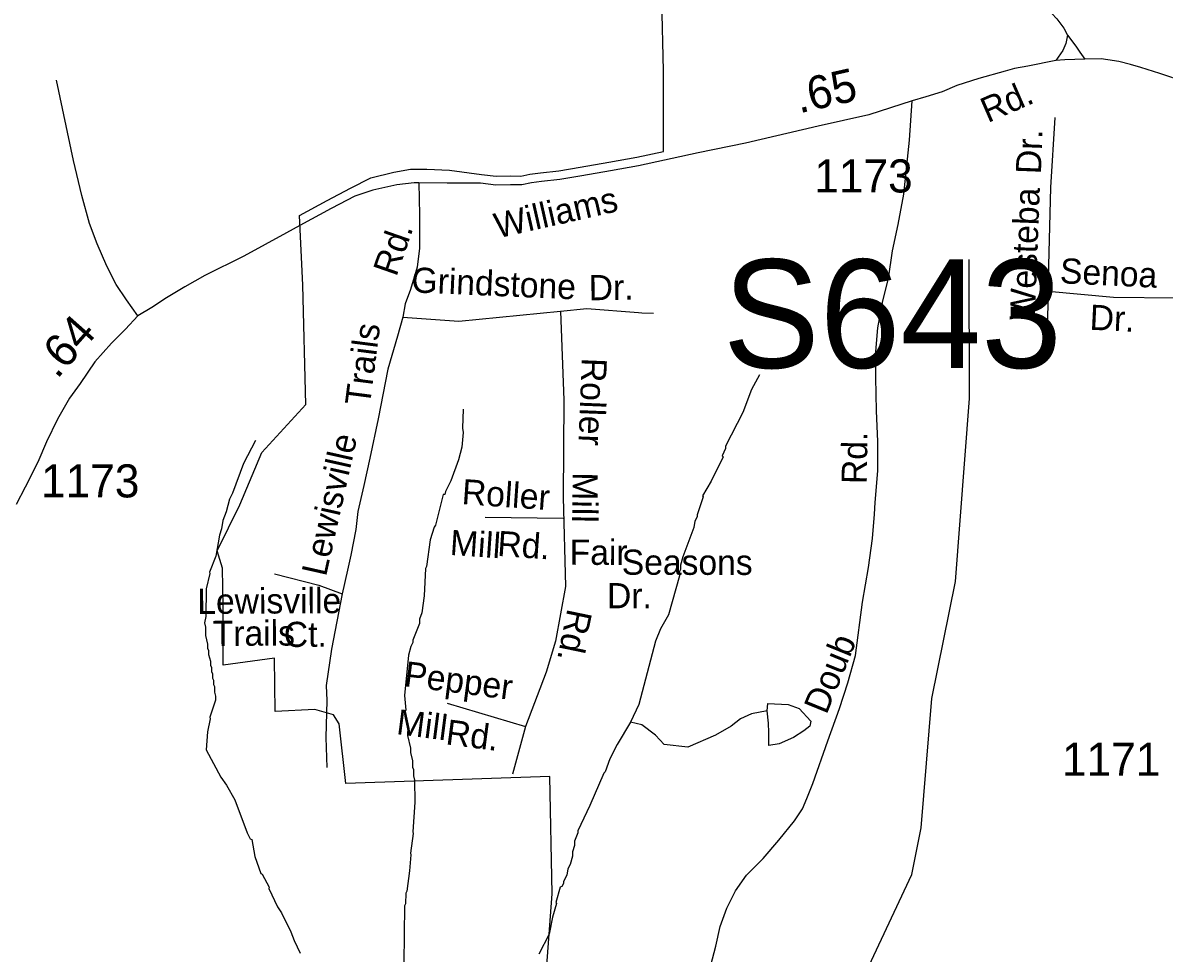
# Model space of a CAD drawing. Extents: x 1547597 to 1699558, y 810033 to 920809.
# Drawn here: x 1572833 to 1577144, y 851331 to 854845 of the extents above; entities that cross this region are included whole.
import ezdxf

# ---------------------------------------------------------------- set-up
doc = ezdxf.new("R2010")
doc.units = 0
for name, color, linetype in [('Exist Boundary Political City Limit New', 7, 'Continuous'), ('Exist Hydrographic Creek Single Shore', 7, 'Continuous'), ('Exist Hydrographic Misc Water Feature', 7, 'Continuous'), ('Exist Road Non-System Type 51', 7, 'Continuous'), ('Exist Road Non-System Type 51 Label', 7, 'Continuous'), ('Exist Road Primary Interstate Structure Ovrhead Sign Number Label', 7, 'Continuous'), ('Exist Road Primary US Ramp 1 Lane  Attributed', 7, 'Continuous'), ('Exist Road Secondary Mileage Hundredths English Label', 7, 'Continuous'), ('Exist Road Secondary Type 51 Attributed', 7, 'Continuous'), ('Exist Road Secondary Type 51 Label', 7, 'Continuous'), ('Exist Road Secondary Type 51 Number Label', 7, 'Continuous'), ('Map Preparation Boundary City Limit Buffer Line', 7, 'Continuous')]:
    doc.layers.add(name, color=color, linetype=linetype)

msp = doc.modelspace()

# ---------------------------------------------------------------- linework, layer by layer
at = {"layer": 'Exist Boundary Political City Limit New'}
msp.add_line((1574805.4, 851192.3), (1574832.2, 851554.6), dxfattribs=at)
msp.add_lwpolyline([(1574832.2, 851554.6), (1574824.2, 851997.9), (1574053, 851971), (1574027.8, 852197.3), (1574006.6, 852230.7), (1573936.2, 852251.3), (1573785.5, 852243.2), (1573783.2, 852444.9), (1573589.4, 852417.9), (1573590.2, 852639), (1573587, 852784.3), (1573566.9, 852850), (1573653.1, 853024.1), (1573735.3, 853221.6), (1573901.9, 853403.3), (1573890.4, 853853.6), (1573877.7, 854116.6), (1573982.1, 854173.1), (1574071.1, 854219.9), (1574147, 854258.7), (1574234.2, 854280.8), (1574296.8, 854292.6), (1574358.4, 854291.8), (1574445.1, 854288.6), (1574565.7, 854271.9), (1574621, 854265.3), (1574675.4, 854266.4), (1574714.3, 854265.9), (1574747.9, 854272.9), (1574787.9, 854278.7), (1574857.3, 854285.4), (1574938.4, 854300), (1575046.9, 854318.5), (1575152.4, 854336.8), (1575252.9, 854358.6), (1575252.4, 854662.9), (1575247, 854934.5)], dxfattribs=at)
at = {"layer": 'Exist Hydrographic Creek Single Shore'}
msp.add_lwpolyline([(1572780, 849528.5), (1573518.6, 849772.1), (1573732.5, 850003.6), (1573884.4, 850151.5), (1574087.9, 850283.4), (1574357.2, 850346.4), (1574788.5, 850389.2), (1575358.5, 850591.1), (1575509.5, 850679.9), (1575750.8, 850960.4), (1575874.1, 851087.1), (1575927.5, 851209.3), (1576009.4, 851241), (1576190.5, 851628), (1576226.4, 851804.6), (1576266.5, 852292.9), (1576356.4, 852734.2), (1576408.5, 853425.8), (1576407.5, 853951)], dxfattribs=at)
at = {"layer": 'Exist Hydrographic Misc Water Feature'}
for points in [[(1575616.2, 853515.6), (1575585.6, 853460), (1575552.5, 853372.4), (1575487, 853245.3), (1575486.9, 853237.3), (1575474.6, 853209.5), (1575478.5, 853205.4), (1575433.4, 853114), (1575400.8, 853058.4), (1575402.3, 853054), (1575380, 852986.8), (1575379.9, 852978.8), (1575371.7, 852962.9), (1575367.4, 852939), (1575326.1, 852827.5), (1575317.7, 852795.6), (1575317.6, 852779.6), (1575313.5, 852771.7), (1575313.2, 852755.7), (1575271.5, 852608.3), (1575241.8, 852555.2), (1575222.3, 852509), (1575159.5, 852269.8), (1575128.4, 852202.8)], [(1574496.8, 853385.7), (1574494, 853313.7), (1574495.8, 853297.7), (1574491.2, 853241.8), (1574478.6, 853194), (1574449.7, 853114.4), (1574429.2, 853074.7), (1574427, 853062.7), (1574421.1, 853062.8), (1574391.6, 852947.2), (1574386.4, 852939.9), (1574371, 852891.5), (1574357.8, 852791.7), (1574353.7, 852783.7), (1574348.5, 852679.9), (1574339.8, 852616), (1574331.5, 852592.1), (1574331.3, 852576.1), (1574306.5, 852512.4), (1574306.4, 852504.4), (1574298.2, 852488.6), (1574289.9, 852456.7), (1574274, 852304.3), (1574279.4, 852248.9), (1574277.3, 852243.3), (1574286.7, 852184.9), (1574286.2, 852152.9), (1574297.7, 852104.7), (1574297.5, 852088.8), (1574305.1, 852056.7), (1574304.9, 852032.7), (1574308.8, 852024.6), (1574308.5, 852000.6), (1574312.3, 851984.6), (1574313.3, 851900.6), (1574305.9, 851788.8), (1574307.8, 851782), (1574297, 851708.9), (1574298.8, 851702.1), (1574293.3, 851641.7), (1574283.3, 851565.2), (1574279.2, 851557.2), (1574278.8, 851517.2), (1574274.7, 851509.3), (1574272.1, 851293.4)], [(1573711.6, 853267.6), (1573666.6, 853180.2), (1573625.3, 853068.8), (1573613, 853045), (1573600.4, 852997.1), (1573588, 852965.3), (1573583.6, 852933.4), (1573575.4, 852909.5), (1573562.4, 852829.7), (1573537.8, 852770), (1573539, 852765.3), (1573525, 852706.2), (1573523.8, 852602.3), (1573519.4, 852578.3), (1573523.2, 852562.3), (1573522.9, 852530.3), (1573530.5, 852498.2), (1573530.3, 852482.3), (1573534.2, 852474.2), (1573534, 852458.2), (1573541.8, 852434.1), (1573541.6, 852418.1), (1573545.5, 852410.1), (1573545.3, 852394.1), (1573549.2, 852386), (1573549, 852370), (1573552.9, 852362), (1573552.7, 852346), (1573556.7, 852337.9), (1573556.4, 852316), (1573560.2, 852302), (1573560.1, 852286), (1573539.2, 852222.2), (1573540.5, 852215.9), (1573530.6, 852166.4), (1573525.8, 852098.4), (1573580.6, 851995.8), (1573602.2, 851965.6), (1573633.6, 851909.2), (1573680, 851784.7), (1573691.8, 851762.5), (1573697.7, 851760.4), (1573709, 851696.3), (1573732.2, 851632.1), (1573737.5, 851629.6), (1573763.6, 851579.7), (1573762, 851574.6), (1573794.7, 851505.3), (1573810.4, 851483.1), (1573845.6, 851410.8), (1573857.2, 851378.6), (1573880.6, 851330.3)], [(1575644.7, 852245.4), (1575585.8, 852235), (1575543.5, 852215.6), (1575508, 852188.6), (1575449.7, 852153.8), (1575344.3, 852108.4), (1575255.6, 852118.5), (1575222.6, 852154), (1575170.6, 852193.7), (1575128.4, 852202.8)], [(1575644.7, 852245.4), (1575647.2, 852273.3), (1575723.3, 852269.5), (1575765.1, 852254.3), (1575809.4, 852207.3), (1575805.6, 852188.3), (1575782.8, 852170.5), (1575743.5, 852145.2), (1575690.3, 852121.1), (1575651, 852114.7), (1575651, 852164.2), (1575649.7, 852199.7), (1575644.7, 852245.4)], [(1575128.4, 852202.8), (1575077.7, 852118.9), (1575049.8, 852064.4), (1575032.5, 852015.6), (1575027.3, 852010.2), (1574975, 851888.3), (1574929.9, 851792.9), (1574929.8, 851784.9), (1574917.4, 851753.1), (1574917.2, 851737.1), (1574909, 851713.3), (1574908.8, 851697.3), (1574900.4, 851665.4), (1574892.2, 851649.5), (1574887.9, 851625.5), (1574875.7, 851601.7), (1574875.6, 851593.7), (1574869.4, 851581.8), (1574862.8, 851580), (1574846.6, 851522.1), (1574848.3, 851517.7), (1574834, 851466.3), (1574821.2, 851402.4), (1574782.4, 851327)]]:
    msp.add_lwpolyline(points, dxfattribs=at)
at = {"layer": 'Exist Road Non-System Type 51'}
for p, q in [((1574579.9, 852977), (1574873.6, 852974.1)), ((1574435.8, 852275.5), (1574732.3, 852187))]:
    msp.add_line(p, q, dxfattribs=at)
for points in [[(1573267.7, 853737.5), (1573224.6, 853798.2), (1573185.5, 853856.8), (1573150.5, 853925.4), (1573113.6, 854009.8), (1573084.7, 854086.4), (1573056.2, 854192.9), (1573024.1, 854325.4), (1572960.4, 854628.4)], [(1575431.2, 851285.1), (1575450.3, 851356.8), (1575467.2, 851430.7), (1575492.2, 851500.2), (1575525.4, 851565.8), (1575566.2, 851625.2), (1575629.1, 851688.4), (1575688.1, 851757.6), (1575747.3, 851830.6), (1575778, 851876.2), (1575794.9, 851915.4), (1575817.4, 851971), (1575873.7, 852132.1), (1575918, 852254.3), (1575949.6, 852352), (1575978, 852454.7), (1576004.2, 852656.3), (1576027.2, 852787.1), (1576042.8, 852897.1), (1576049.6, 852988.9), (1576052.8, 853032.9), (1576062.6, 853152.8), (1576062, 853262.9), (1576057.8, 853379), (1576055.5, 853505.1), (1576053.6, 853588.5), (1576062.1, 853693.3), (1576081.5, 853795.2), (1576103.3, 853879), (1576117.5, 853983.8), (1576139.2, 854083.4), (1576160.8, 854197.1), (1576181.7, 854401.2), (1576192.2, 854550.5)], [(1576705.4, 853829.5), (1576716.5, 854223.4), (1576732, 854486.8)], [(1574329.3, 854240.7), (1574331.3, 854119.9), (1574330.7, 853994.1), (1574322.6, 853921.6), (1574296.8, 853837.5), (1574276.8, 853782.9), (1574268.3, 853733.5)], [(1576705.4, 853829.5), (1576701, 853635.8)], [(1577185.2, 853804.6), (1576953.1, 853807.4), (1576705.4, 853829.5)], [(1574268.3, 853733.5), (1574479.5, 853718.4), (1574863.5, 853755.3)], [(1574863.5, 853755.3), (1574876.5, 853419.8), (1574873.8, 853053.1), (1574883.2, 852715.5), (1574844.7, 852509.1), (1574809.5, 852391.7), (1574732.3, 852187), (1574682.5, 852006.8)], [(1574863.5, 853755.3), (1574963.7, 853765.4), (1575158.4, 853750.2), (1575170.8, 853749.7), (1575214.9, 853747.8)], [(1574268.3, 853733.5), (1574247.6, 853661.2), (1574212, 853537), (1574174.6, 853348.5), (1574143.7, 853200.8), (1574121.6, 853097.1), (1574098.1, 852998.4), (1574090.8, 852930.9), (1574071.3, 852834.3), (1574059.5, 852777.3), (1574039.3, 852688.4)], [(1573783.6, 852763.3), (1573950.5, 852720.3), (1574039.3, 852688.4)], [(1574039.3, 852688.4), (1573999.2, 852479.4), (1573979.1, 852341.8), (1573980.7, 852284.8), (1573977.4, 852145.5), (1573980.7, 852031.4)]]:
    msp.add_lwpolyline(points, dxfattribs=at)
at = {"layer": 'Exist Road Primary US Ramp 1 Lane  Attributed'}
for points in [[(1575862.8, 855406.7), (1576130.7, 855261.9), (1576247.6, 855177), (1576494, 855033.3), (1576622.2, 854959.8), (1576700.6, 854899.7), (1576738.7, 854860.2), (1576765.2, 854824.8), (1576779.3, 854798.8)], [(1576779.3, 854798.8), (1576772.9, 854767), (1576761.1, 854740.4), (1576735.1, 854702.1)], [(1576779.3, 854798.8), (1576810, 854757), (1576825.9, 854734), (1576844.2, 854708)]]:
    msp.add_lwpolyline(points, dxfattribs=at)
at = {"layer": 'Exist Road Secondary Type 51 Attributed'}
for points in [[(1576735.1, 854702.1), (1576629.4, 854681.5), (1576579.3, 854672.8), (1576543.7, 854661.7), (1576444, 854634.6), (1576361.6, 854607.6), (1576306.1, 854584.8), (1576243.9, 854565.6), (1576192.2, 854550.5), (1576028, 854497.9), (1575837.2, 854454.7), (1575562.2, 854390.6), (1575383.5, 854353.2), (1575158.9, 854304.4), (1575052.5, 854285.9), (1574944.1, 854267.5), (1574861.9, 854252.7), (1574791.9, 854245.7), (1574753.8, 854240.3), (1574717.5, 854232.8), (1574675.6, 854233.3), (1574619.4, 854232.2), (1574561.6, 854239), (1574435.3, 854238.7), (1574329.3, 854240.7), (1574310.6, 854240.7), (1574246.2, 854233.4), (1574155.6, 854213.2), (1574086.8, 854189.8), (1573998, 854143.2), (1573879.5, 854079.1), (1573828.6, 854051.5), (1573667.2, 853963.8), (1573520.2, 853889.9), (1573444.2, 853847), (1573375.3, 853806.3), (1573319.9, 853769.9), (1573267.7, 853737.5), (1573220.9, 853688.2), (1573168.2, 853634.9), (1573105.1, 853563.7), (1573049.9, 853482.6), (1573009.1, 853427.2), (1572963.9, 853347.6), (1572922.7, 853262.2), (1572889.5, 853184.7), (1572842.2, 853091.4), (1572807.3, 853025.8)], [(1576844.2, 854708), (1576769.3, 854705.1), (1576735.1, 854702.1)], [(1577225.2, 854621.3), (1577127.9, 854653.2), (1577055.7, 854676.2), (1577016.7, 854687.4), (1576973.1, 854699.2), (1576931.2, 854705.6), (1576906.4, 854708.6), (1576844.2, 854708)]]:
    msp.add_lwpolyline(points, dxfattribs=at)
at = {"layer": 'Map Preparation Boundary City Limit Buffer Line'}
msp.add_line((1574805.4, 851192.3), (1574832.2, 851554.6), dxfattribs=at)
msp.add_lwpolyline([(1574832.2, 851554.6), (1574824.2, 851997.9), (1574053, 851971), (1574027.8, 852197.3), (1574006.6, 852230.7), (1573936.2, 852251.3), (1573785.5, 852243.2), (1573783.2, 852444.9), (1573589.4, 852417.9), (1573590.2, 852639), (1573587, 852784.3), (1573566.9, 852850), (1573653.1, 853024.1), (1573735.3, 853221.6), (1573901.9, 853403.3), (1573890.4, 853853.6), (1573877.7, 854116.6), (1573982.1, 854173.1), (1574071.1, 854219.9), (1574147, 854258.7), (1574234.2, 854280.8), (1574296.8, 854292.6), (1574358.4, 854291.8), (1574445.1, 854288.6), (1574565.7, 854271.9), (1574621, 854265.3), (1574675.4, 854266.4), (1574714.3, 854265.9), (1574747.9, 854272.9), (1574787.9, 854278.7), (1574857.3, 854285.4), (1574938.4, 854300), (1575046.9, 854318.5), (1575152.4, 854336.8), (1575252.9, 854358.6), (1575252.4, 854662.9), (1575247, 854934.5)], dxfattribs=at)

# ---------------------------------------------------------------- texts
at = {"layer": 'Exist Road Non-System Type 51 Label'}
for s, rotation, p in [('Dr.', 87.812, (1576678.6, 854272)), ('Westeba', 87.812, (1576655.5, 853719.6)), ('Rd.', 70.7445, (1574243.6, 853882.9)), ('Senoa', 357.2704, (1576749, 853861.4)), ('Grindstone', 357.534, (1574299.3, 853826.8)), ('Dr.', 0.8733, (1574971.1, 853796.6)), ('Dr.', 357.2704, (1576861.2, 853685.7)), ('Trails', 82.6954, (1574143.7, 853395.8)), ('Roller', 267.7378, (1574944.6, 853580.7)), ('Lewisville', 77.3581, (1573977.9, 852750.4)), ('Rd.', 89.2073, (1576020.8, 853102.2)), ('Mill', 269.2985, (1574910, 853147.5)), ('Roller', 356.0521, (1574489, 853027)), ('Mill', 356.0521, (1574444.2, 852835.1)), ('Rd.', 356.0521, (1574623.3, 852831.5)), ('Fair', 359.9254, (1574898.5, 852797.5)), ('Seasons', 359.9254, (1575095.2, 852760)), ('Lewisville', 0.3352, (1573492.1, 852611.9)), ('Dr.', 359.9254, (1575039.5, 852633.6)), ('Rd.', 258.3368, (1574890.8, 852635.2)), ('Trails', 0.3352, (1573550.5, 852490.9)), ('Ct.', 0.3352, (1573818.9, 852487)), ('Doub', 67.8735, (1575868.5, 852228.8)), ('Pepper', 352.6425, (1574270.1, 852339.6)), ('Mill', 352.6425, (1574241.1, 852158.4)), ('Rd.', 352.6425, (1574427.5, 852119.8))]:
    msp.add_text(s, height=95, rotation=rotation, dxfattribs=at).set_placement(p)
at = {"layer": 'Exist Road Primary Interstate Structure Ovrhead Sign Number Label'}
msp.add_text('S643', height=410.1, dxfattribs=at).set_placement((1575477.3, 853541.1))
at = {"layer": 'Exist Road Secondary Mileage Hundredths English Label'}
for s, rotation, p in [('.65', 12.7572, (1575765.5, 854502.5)), ('.64', 48.4516, (1572962, 853496.4))]:
    msp.add_text(s, height=125, rotation=rotation, dxfattribs=at).set_placement(p)
at = {"layer": 'Exist Road Secondary Type 51 Label'}
for s, rotation, p in [('Rd.', 23.5528, (1576477.7, 854465.8)), ('Williams', 12.7572, (1574625.9, 854030.2))]:
    msp.add_text(s, height=95, rotation=rotation, dxfattribs=at).set_placement(p)
at = {"layer": 'Exist Road Secondary Type 51 Number Label'}
for s, p in [('1173', (1575822.4, 854204)), ('1173', (1572901.4, 853052.1)), ('1171', (1576758, 852000.7))]:
    msp.add_text(s, height=125, dxfattribs=at).set_placement(p)

doc.saveas('drawing.dxf')
